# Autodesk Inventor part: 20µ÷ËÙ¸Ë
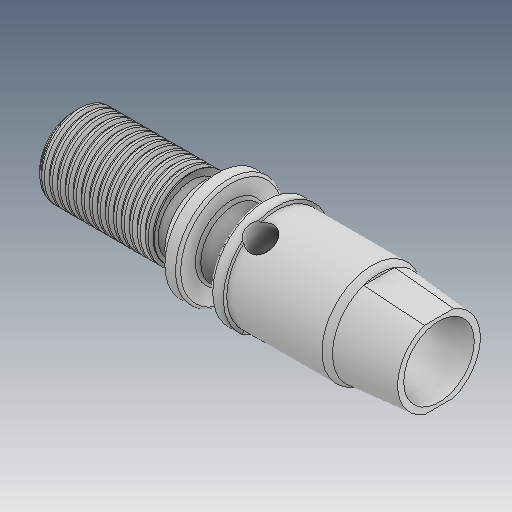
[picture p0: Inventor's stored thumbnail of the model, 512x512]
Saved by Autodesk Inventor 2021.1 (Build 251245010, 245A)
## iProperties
Created: 2019-12
Part Number: 20µ÷ËÙ¸Ë
Material: Ogólny
Document SubType Name: Modeling
Designer: user
Density: 1 g/cm^3
Appearance: Domyślna
Author: user
Revision Number: ÈÎºÎ
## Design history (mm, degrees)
feature "ÊäÈë1"
node "Bryła1"
